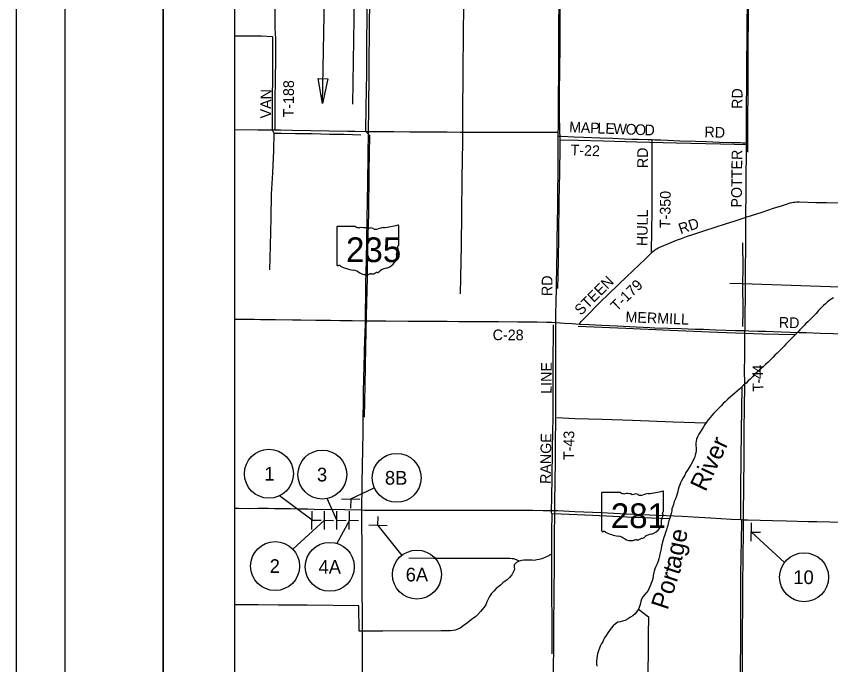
# Model space of a CAD drawing. Extents: x 0 to 680, y 0 to 834.
# Drawn here: x 0 to 166.4, y 90.7 to 223.2 of the extents above; entities that cross this region are included whole.
import ezdxf

# ---------------------------------------------------------------- set-up
doc = ezdxf.new("R2010")
doc.units = 0
for name, color, linetype in [('GM_X_County_Road', 7, 'Continuous'), ('GM_X_County_Road_Text', 7, 'Continuous'), ('GM_X_Interstate_Route', 7, 'Continuous'), ('GM_X_Major_River', 7, 'Continuous'), ('GM_X_Major_River_Text', 7, 'Continuous'), ('GM_X_Minor_River', 7, 'Continuous'), ('GM_X_State_Location', 7, 'Continuous'), ('GM_X_State_Route', 7, 'Continuous'), ('GM_X_State_Shield', 7, 'Continuous'), ('GM_X_Township_Road', 7, 'Continuous'), ('GM_X_Township_Road_Text', 7, 'Continuous'), ('SH_Border', 7, 'Continuous'), ('SH_Cut_Line', 7, 'Continuous'), ('SH_Text', 7, 'Continuous')]:
    doc.layers.add(name, color=color, linetype=linetype)

msp = doc.modelspace()

# ---------------------------------------------------------------- linework, layer by layer
at = {"layer": 'GM_X_County_Road'}
for points in [[(44.69, 161.35), (46.07, 161.33), (47.26, 161.32), (48.69, 161.31), (49.88, 161.28), (52.99, 161.27), (56.45, 161.22), (58.12, 161.19), (61.22, 161.13), (64.21, 161.1), (66.11, 161.07), (68.62, 161.02), (71.25, 160.98), (71.35, 160.98)], [(71.35, 160.98), (73.16, 160.98), (75.54, 160.96), (80.08, 160.94), (84.25, 160.92), (88.07, 160.89), (90.34, 160.88), (95.12, 160.84), (98.58, 160.82), (102.52, 160.79), (105.5, 160.77), (106.45, 160.78), (108.36, 160.74), (108.93, 160.73), (109.44, 160.71), (110.27, 160.65)], [(110.27, 160.65), (112.06, 160.51), (113.6, 160.41), (115.07, 160.33)], [(115.07, 160.33), (115.27, 160.32), (117.06, 160.24), (119.68, 160.11), (121.23, 160.03), (122.9, 159.95), (124.09, 159.89), (125.29, 159.84), (129.46, 159.61), (130.41, 159.57), (135.9, 159.4), (138.76, 159.31), (140.43, 159.26), (142.94, 159.17), (146.99, 159.03), (148.42, 158.99), (148.93, 158.98)], [(148.93, 158.98), (149.74, 158.96), (151.64, 158.89), (153.2, 158.84), (154.75, 158.78), (156.29, 158.75), (160, 158.63), (161.43, 158.58), (164.29, 158.48), (166.91, 158.38), (168.34, 158.34), (170.85, 158.25), (173.59, 158.14), (175.02, 158.09), (178.24, 157.97), (186.12, 157.68), (187.64, 157.62)]]:
    msp.add_lwpolyline(points, dxfattribs=at)
at = {"layer": 'GM_X_Interstate_Route'}
msp.add_lwpolyline([(44.69, 394.07), (374.69, 394.07), (374.69, 64.07), (44.69, 64.07)], close=True, dxfattribs=at)
at = {"layer": 'GM_X_Major_River'}
for points in [[(166.98, 165.7), (166.35, 165.28), (165.81, 164.85), (165.34, 164.44), (164.96, 164.12), (164.42, 163.56), (163.95, 163.09), (163.44, 162.49), (163.03, 162.1), (162.61, 161.62), (162.14, 161.17), (161.73, 160.77), (161.37, 160.42), (161.03, 160.05), (160.52, 159.54), (160.12, 159.14), (159.66, 158.59), (158.79, 157.73), (158.36, 157.28), (157.8, 156.76), (157.29, 156.25), (156.92, 155.84), (156.44, 155.35), (155.93, 154.82), (155.48, 154.39), (155.04, 153.95), (154.59, 153.47), (154.06, 152.95), (153.65, 152.51), (153.09, 152.05), (152.63, 151.58), (152.17, 151.2), (151.81, 150.93), (151.4, 150.52), (150.89, 150.01), (150.44, 149.57), (149.97, 149.09), (149.6, 148.72), (149.14, 148.26), (148.64, 147.83), (148.27, 147.48), (147.84, 147.12), (147.34, 146.62), (146.86, 146.2), (146.37, 145.79), (145.97, 145.43), (145.4, 144.96), (144.87, 144.45), (144.49, 144.09), (144.05, 143.64), (142.96, 142.53)], [(142.96, 142.53), (142.53, 142.1), (142.15, 141.61), (141.81, 141.22), (141.42, 140.75), (141.06, 140.29), (140.73, 139.81), (140.42, 139.33), (140.09, 138.76), (139.75, 138.25), (139.49, 137.79), (139.24, 137.29), (139.02, 136.81), (138.93, 136.42), (138.86, 135.97), (138.86, 135.5), (138.94, 134.94), (138.94, 134.49), (138.89, 134.01), (138.77, 133.55), (138.57, 133.01), (138.34, 132.49), (138.12, 132.04), (137.84, 131.55), (137.52, 130.99), (137.17, 130.47), (136.86, 129.97), (136.6, 129.46), (136.32, 128.91), (135.96, 128.32), (135.72, 127.87), (135.58, 127.45), (135.38, 126.96), (135.24, 126.5), (135.18, 126.12), (135.05, 125.64), (134.9, 125.12), (134.7, 124.62), (134.47, 124.09), (134.32, 123.48), (134.18, 123.05), (134, 122.54), (133.95, 122.16), (133.84, 121.62), (133.71, 121.16), (133.53, 120.67), (133.37, 120.14), (133.23, 119.56), (133.14, 119.17), (133.03, 118.79), (132.86, 118.26), (132.69, 117.75), (132.51, 117.23), (132.36, 116.71), (132.22, 116.23), (132.09, 115.85), (131.98, 115.39), (131.88, 114.98), (131.76, 114.41), (131.64, 113.82), (131.53, 113.33), (131.43, 112.86), (131.34, 112.34), (131.21, 111.87), (131, 111.34), (130.71, 110.79), (130.52, 110.27), (130.36, 109.8), (130.24, 109.31), (130.14, 108.83), (130.09, 108.32), (129.97, 107.86), (129.78, 107.37), (129.59, 106.97), (129.36, 106.37), (129.1, 105.89), (128.78, 105.44), (128.45, 105.06), (128.06, 104.6), (127.79, 104.09), (127.62, 103.6), (127.47, 103), (127.31, 102.42), (127.13, 102.03), (126.83, 101.56), (126.45, 101.11), (125.97, 100.71), (125.49, 100.4), (124.88, 100.04), (124.43, 99.77), (123.9, 99.61), (123.38, 99.5), (122.95, 99.37), (122.46, 99.05), (121.97, 98.63), (121.56, 98.15), (121.22, 97.7), (120.86, 97.24), (120.52, 96.69), (120.18, 96.22), (119.99, 95.8)], [(119.99, 95.8), (119.84, 95.39), (119.62, 95.02), (119.33, 94.53), (119.16, 94.08), (118.97, 93.54), (118.77, 92.95), (118.69, 92.51), (118.63, 92.03), (118.58, 91.46), (118.59, 90.91), (118.61, 90.4)]]:
    msp.add_lwpolyline(points, dxfattribs=at)
at = {"layer": 'GM_X_Minor_River'}
for points in [[(92.3, 320.37), (92.2, 311.07), (92.09, 303.82), (91.99, 294.71), (91.89, 283.03), (91.78, 275.5), (91.7, 266.96), (91.6, 257.68), (91.54, 248.37), (91.45, 240.55), (91.44, 230.55), (91.36, 219.85), (91.29, 211.97), (91.2, 203.05), (91.21, 197.47), (91.04, 190.19), (90.98, 182.86), (90.9, 176.37), (90.73, 166.48)], [(149.64, 235.45), (149.57, 227.15), (149.53, 213.12), (149.42, 196.92), (149.44, 195.48)], [(110.7, 167.6), (110.82, 173.02), (110.9, 178.6), (110.93, 185.45), (111.06, 191.27), (111.12, 196.57), (111.12, 197.94), (111.04, 202.58), (111.03, 207.65), (111.14, 217.07), (111.18, 222.25), (111.21, 228.21)], [(71.71, 227.13), (71.59, 218.3), (71.57, 211.69), (71.43, 204.6), (71.38, 199.77), (72.18, 198.96), (72.04, 191.47), (71.97, 182.83), (71.76, 176.4), (71.68, 169.69), (71.52, 162.05), (71.36, 155.58), (71.21, 147.86), (71.09, 141.27)], [(44.69, 219.23), (46.26, 219.23), (50.09, 219.21), (52.33, 219.07), (52.39, 215.63), (52.33, 210.78), (52.31, 206.5), (52.29, 201.79), (52.31, 200.04), (52.62, 199.34), (54.19, 199.32), (57.04, 199.26), (60.45, 199.25), (64.02, 199.11), (66.99, 199.14), (70.39, 198.98)], [(52.62, 199.34), (52.54, 195.77), (52.38, 191.22), (52.12, 186.88), (52.04, 182.05), (51.87, 176.34), (51.74, 171.44)], [(143.92, 197.1), (134.84, 197.28), (126.8, 197.53), (120.03, 197.68), (114.76, 197.85), (111.12, 197.94)], [(149.42, 196.92), (143.92, 197.1)], [(148.42, 176.94), (148.45, 171.85), (148.42, 168.53), (148.47, 163.06), (148.44, 159.82)], [(168.34, 166.54), (168.3, 167.86), (158.35, 168.24), (148.42, 168.53), (145.85, 168.59)], [(109.75, 160.14), (109.62, 151.56), (109.64, 145.72), (109.62, 141.38), (109.49, 134.83), (109.44, 128.69), (109.41, 125.19), (109.34, 121.82), (109.43, 121.55), (109.35, 117.9), (109.35, 113.27), (109.37, 109.26), (109.4, 104.45), (109.43, 100.49), (109.42, 92.94)], [(143.33, 158.61), (133.64, 159), (124.59, 159.44), (114.81, 159.81)], [(159.16, 158.1), (152.47, 158.25), (143.33, 158.61)], [(148.27, 147.48), (148.14, 138.43), (148.01, 126.88), (148.02, 120.58), (148.21, 120.13), (148.18, 119.76), (148.01, 109.13), (148.02, 96.79), (147.95, 88.72), (147.85, 83.77), (147.87, 81.22), (142.15, 81.47)], [(140.91, 140.07), (134.23, 140.31), (125.95, 140.59), (119.72, 140.8), (114.13, 140.99), (110.44, 141.17)], [(133.49, 120.52), (126.13, 120.82), (117.85, 121.22), (111.35, 121.46), (109.43, 121.55)], [(109.35, 113.27), (108.48, 112.85), (107.88, 112.54), (107.38, 112.34), (106.85, 112.2), (106.4, 112.11), (105.83, 112.03), (105.42, 112.04), (104.97, 112.06), (104.24, 112.07), (103.72, 112.07), (103.25, 112.02), (102.77, 111.89), (102.24, 111.61), (101.78, 111.09), (101.76, 110.66), (101.81, 110.25), (101.7, 109.86), (101.28, 109.05), (100.79, 108.56), (100.29, 108.07), (99.88, 107.77), (99.45, 107.46), (98.96, 106.96), (98.08, 106.27), (97.61, 105.76), (97.13, 105.25), (96.83, 104.88), (96.57, 104.4), (96.36, 103.96), (96.19, 103.54), (95.98, 102.96), (95.65, 102.44), (95.25, 102.05), (94.88, 101.55), (94.33, 100.97), (93.89, 100.57), (93.44, 100.19), (93.05, 99.93), (92.59, 99.59), (92.12, 99.19), (91.57, 98.85), (91.17, 98.5), (90.69, 98.18), (90.22, 97.94), (89.72, 97.8), (89.27, 97.71), (88.77, 97.64), (88.31, 97.63), (87.82, 97.63), (86.81, 97.64)], [(99.4, 112.4), (85.35, 112.43), (80.22, 112.51)], [(102.77, 111.89), (102.21, 112.11), (101.69, 112.32), (101.31, 112.35), (100.86, 112.41), (100.35, 112.43), (99.9, 112.42), (99.4, 112.4)], [(86.81, 97.64), (74.91, 97.55), (70.08, 97.53), (70.03, 102.73), (59.45, 102.85), (53.62, 102.87), (49.42, 102.96), (44.69, 102.97)], [(127.13, 102.03), (129.17, 100.48), (129.11, 96.91), (129.11, 92.94), (129.01, 86.48), (128.98, 82.05), (128.91, 76.47), (128.8, 72.83)]]:
    msp.add_lwpolyline(points, dxfattribs=at)
at = {"layer": 'GM_X_State_Route'}
for points in [[(70.65, 122.33), (70.65, 123.54), (70.68, 126.41), (70.7, 128.08), (70.74, 131.18), (70.82, 134.88), (70.87, 137.98), (70.92, 141.57), (70.94, 143.95), (70.96, 145.5), (70.97, 146.94), (71.02, 148.73), (71.12, 152.19), (71.16, 153.74), (71.19, 154.69), (71.26, 156.96), (71.34, 160.18), (71.35, 160.98), (71.35, 161.85), (71.43, 167.1), (71.46, 168.65), (71.54, 173.31), (71.71, 181.78), (71.84, 189.18), (71.93, 194.79), (71.99, 199.71), (72, 201.12), (72.03, 202.79), (72.04, 204.58), (72.05, 205.77), (72.09, 210.19), (72.1, 211.98), (72.14, 214.96), (72.17, 219.02), (72.2, 222.48), (72.23, 224.99)], [(44.69, 122.67), (45.39, 122.67), (47.42, 122.66), (49.33, 122.67), (51.47, 122.67), (52.79, 122.66), (54.46, 122.64), (56.01, 122.62), (57.92, 122.58), (59.59, 122.55), (60.9, 122.53), (67.11, 122.4), (70.65, 122.33)], [(70.88, 64.07), (70.87, 69.59), (70.85, 72.34), (70.83, 74.48), (70.8, 80.21), (70.8, 81.89), (70.79, 83.67), (70.79, 84.03), (70.78, 85.59), (70.77, 88.09), (70.76, 90.12), (70.73, 95.37), (70.73, 98.36), (70.69, 108.38), (70.68, 110.89), (70.68, 112.68), (70.66, 115.31), (70.64, 119.25), (70.65, 121.99), (70.65, 122.33)], [(70.65, 122.33), (71.16, 122.32), (73.67, 122.31), (78.2, 122.3), (80.71, 122.29), (87.16, 122.27), (89.9, 122.28), (93.72, 122.27), (103.39, 122.26), (105.53, 122.26), (107.68, 122.25), (109.12, 122.24), (110.09, 122.21)], [(110.09, 122.21), (110.67, 122.19), (114.13, 122.05), (119.61, 121.8), (124.62, 121.57), (127.72, 121.44), (132.85, 121.21), (134.39, 121.13), (136.06, 121.05), (138.33, 120.92), (141.9, 120.72), (146.07, 120.48), (148.1, 120.37), (148.63, 120.35), (149.53, 120.32), (154.54, 120.19), (157.4, 120.12), (161.82, 120), (163.61, 119.95), (166.23, 119.89), (169.45, 119.81)]]:
    msp.add_lwpolyline(points, dxfattribs=at)
at = {"layer": 'GM_X_State_Shield'}
for p, q in [((65.49, 180.12), (65.49, 172.44)), ((69.32, 180.25), (65.62, 180.25)), ((78.15, 176.42), (78.15, 180.44)), ((78.15, 176.42), (78.15, 176.42)), ((119.63, 125.77), (119.63, 118.08)), ((123.46, 125.9), (119.75, 125.9)), ((132.29, 122.07), (132.29, 126.09)), ((132.28, 122.07), (132.29, 122.07))]:
    msp.add_line(p, q, dxfattribs=at)
for centre, major_axis, start_param, end_param in [((65.64, 180.14), (0.147, 0), 1.712693, 3.28349), ((70.2, 181.15), (1.42, 0), 4.042523, 4.731795), ((70.68, 175.94), (5.11, 0), 1.404758, 1.657858), ((71.83, 180.18), (0.41, 0), 3.836095, 5.185415), ((72.44, 179.29), (0.853, 0), 0.950623, 2.079405), ((73.54, 180.51), (1.03, 0), 4.081561, 5.145723), ((75.35, 177.91), (2.7, 0), 1.699011, 2.107814), ((73.64, 190.73), (13.42, 0), 4.814394, 5.042369), ((78.01, 180.46), (0.141, 0), 6.141152, 7.989035), ((78.65, 174.74), (0.952, 0), 2.387724, 3.262537), ((78.11, 176.13), (0.218, 0), 1.883978, 3.671073), ((76.73, 175.62), (1.31, 0), 5.934695, 6.695948), ((78, 176.41), (0.151, 0), 5.05454, 6.418171), ((74.39, 174.23), (3.36, 0), 5.101752, 6.440018), ((65.64, 172.42), (0.148, 0), 3.00124, 4.508301), ((65.66, 173.21), (1.13, 0), 4.665946, 4.897461), ((65.89, 171.99), (0.407, 0), 0.519207, 1.627899), ((71.03, 178.9), (9.69, 0), 4.195997, 4.488961), ((75.81, 170.28), (1.84, 0), 1.647645, 2.488434), ((68.14, 168.98), (3.03, 0), 0.823519, 1.323587), ((71.42, 171.96), (1.92, 0), 4.026481, 4.996735), ((72.53, 169.3), (1.58, 0), 1.495662, 1.94098), ((72.67, 171.38), (1.03, 0), 4.691044, 5.507374), ((73.6, 170.64), (0.289, 0), 1.147584, 2.315152), ((73.48, 171.69), (1.08, 0), 4.937069, 5.64225), ((119.77, 125.78), (0.147, 0), 1.712693, 3.28349), ((124.34, 126.79), (1.42, 0), 4.042523, 4.731795), ((124.81, 121.58), (5.11, 0), 1.404758, 1.657858), ((125.97, 125.82), (0.41, 0), 3.836095, 5.185415), ((126.58, 124.93), (0.853, 0), 0.950623, 2.079405), ((127.68, 126.15), (1.03, 0), 4.081561, 5.145723), ((129.49, 123.55), (2.7, 0), 1.699011, 2.107814), ((127.78, 136.37), (13.42, 0), 4.814394, 5.042369), ((132.15, 126.1), (0.141, 0), 6.141152, 7.989035), ((132.25, 121.77), (0.218, 0), 1.883978, 3.671073), ((130.87, 121.26), (1.31, 0), 5.934695, 6.695948), ((132.14, 122.05), (0.151, 0), 5.05454, 6.418171), ((128.53, 119.87), (3.36, 0), 5.101752, 6.440018), ((132.79, 120.39), (0.952, 0), 2.387724, 3.262537), ((119.78, 118.06), (0.148, 0), 3.00124, 4.508301), ((119.8, 118.85), (1.13, 0), 4.665946, 4.897461), ((120.03, 117.64), (0.407, 0), 0.519207, 1.627899), ((125.17, 124.54), (9.69, 0), 4.195997, 4.488961), ((122.28, 114.63), (3.03, 0), 0.823519, 1.323587), ((127.74, 116.28), (0.289, 0), 1.147584, 2.315152), ((127.62, 117.34), (1.08, 0), 4.937069, 5.64225), ((129.94, 115.92), (1.84, 0), 1.647645, 2.488434), ((125.56, 117.6), (1.92, 0), 4.026481, 4.996735), ((126.67, 114.94), (1.58, 0), 1.495662, 1.94098), ((126.81, 117.02), (1.03, 0), 4.691044, 5.507374)]:
    msp.add_ellipse(centre, major_axis=major_axis, ratio=0.8, start_param=start_param, end_param=end_param, dxfattribs=at)
at = {"layer": 'GM_X_Township_Road'}
for points in [[(52.91, 199.99), (52.9, 200.37), (52.89, 201.44), (52.93, 205.86), (52.97, 210.52), (53.01, 214.23), (53.05, 215.42), (53.04, 216.5), (53.03, 218.05), (53.01, 218.65), (52.94, 219.72), (52.9, 220.8), (52.88, 221.99), (52.89, 223.31), (52.93, 226.65), (52.96, 228.33), (53.02, 231.91), (53.04, 234.06), (53.07, 236.57), (53.12, 238.17), (53.13, 238.68)], [(110.77, 199.52), (110.78, 200.47), (110.81, 205.48), (110.85, 212.64), (110.87, 214.79), (110.88, 216.46), (110.89, 219.45), (110.9, 222.19), (110.95, 225.06), (110.96, 226.25), (110.98, 230.55), (110.98, 232.82), (110.99, 234.73), (111, 237.11), (111.02, 237.71), (111.04, 237.83), (111.07, 237.99)], [(149.2, 197.36), (149.2, 198.47), (149.23, 200.61), (149.26, 205.86), (149.28, 208.13), (149.33, 213.86), (149.33, 215.65), (149.34, 216.72), (149.39, 222.21), (149.4, 225.2), (149.41, 227.7), (149.42, 229.49), (149.43, 230.93), (149.45, 232.72), (149.46, 235.34), (149.45, 236.02)], [(44.69, 200.06), (49.35, 200.02), (52.1, 200), (52.91, 199.99)], [(52.91, 199.99), (54.01, 199.99), (56.4, 199.94), (67.75, 199.77), (69.18, 199.75), (71.99, 199.71)], [(71.99, 199.71), (72.76, 199.7), (77.18, 199.66), (80.41, 199.64), (88.05, 199.59), (90.68, 199.56), (93.55, 199.55), (97.73, 199.55), (101.31, 199.53), (109.8, 199.54), (110.51, 199.52), (110.77, 199.52)], [(110.27, 160.65), (110.26, 160.98), (110.29, 162.15), (110.35, 165.14), (110.37, 167.4), (110.4, 168.6), (110.45, 171.7), (110.53, 175.88), (110.56, 177.91), (110.62, 180.65), (110.62, 182.08), (110.64, 183.28), (110.66, 184.47), (110.69, 188.29), (110.72, 190.32), (110.72, 191.04), (110.76, 195.57), (110.76, 197.01), (110.75, 198.56), (110.75, 198.72)], [(110.75, 198.72), (110.76, 199.27), (110.77, 199.52)], [(110.75, 198.72), (111.02, 198.72), (111.38, 198.71), (114, 198.6), (115.91, 198.53), (119.26, 198.4), (121.88, 198.3), (124.27, 198.19), (125.82, 198.12), (127.14, 198.1), (129.05, 198.04), (129.96, 198.02)], [(129.94, 188.15), (129.92, 188.64), (129.92, 191.27), (129.93, 195.21), (129.95, 197.72), (129.95, 197.84), (129.96, 198.02)], [(129.96, 198.02), (130.48, 198), (131.68, 197.95), (133.11, 197.9), (135.62, 197.8), (138.84, 197.68), (140.99, 197.62), (143.74, 197.53), (146.37, 197.44), (147.2, 197.42), (147.56, 197.41), (147.99, 197.4), (148.32, 197.39), (148.55, 197.38), (148.79, 197.37), (149.03, 197.37), (149.2, 197.36)], [(149.11, 182.14), (149.12, 183.07), (149.13, 186.65), (149.15, 189.75), (149.2, 195.96), (149.2, 197.27), (149.2, 197.36)], [(129.8, 174.87), (129.8, 175.14), (129.81, 176.1), (129.87, 178.49), (129.93, 184.34), (129.94, 186.97), (129.94, 187.92), (129.94, 188.15)], [(149.11, 182.14), (150.24, 182.51), (152.4, 183.21), (154.78, 183.98), (156.36, 184.48), (157.38, 184.83), (158.17, 185.09), (158.52, 185.18), (158.81, 185.25), (159.11, 185.27), (159.47, 185.29), (160.06, 185.29), (163.4, 185.2), (165.55, 185.16), (168.18, 185.12)], [(129.8, 174.87), (130.12, 175.16), (130.39, 175.39), (130.68, 175.6), (130.88, 175.73), (131.2, 175.9), (131.53, 176.04), (133.51, 176.88), (134.95, 177.46), (135.95, 177.84), (136.96, 178.19), (138.44, 178.67), (140.93, 179.49), (142.63, 180.05), (145.13, 180.87), (146.72, 181.38), (148.99, 182.1), (149.11, 182.14)], [(148.93, 158.98), (148.93, 159.32), (148.98, 161.71), (149.02, 166.48), (149.02, 167.56), (149.03, 169.7), (149.05, 171.85), (149.08, 175.79), (149.08, 178.65), (149.11, 182.14)], [(115.07, 160.33), (115.22, 160.54), (115.29, 160.63), (115.44, 160.82), (115.85, 161.25), (116.85, 162.27), (118.53, 163.97), (119.55, 164.98), (120.92, 166.31), (123.06, 168.38), (124.69, 169.96), (128.57, 173.67), (129.77, 174.84), (129.8, 174.87)], [(110.09, 122.21), (110.09, 122.32), (110.09, 122.78), (110.09, 123.38), (110.15, 128.63), (110.19, 131.85), (110.2, 133.29), (110.22, 136.75), (110.26, 140.21), (110.25, 141.64), (110.26, 143.67), (110.27, 146.42), (110.27, 148.45), (110.28, 150.95), (110.28, 153.1), (110.29, 154.42), (110.29, 156.56), (110.29, 158.35), (110.29, 160.26), (110.27, 160.65)], [(148.77, 138.7), (148.78, 139.39), (148.82, 142.5), (148.83, 144.17), (148.87, 146.79), (148.88, 147.63), (148.86, 148.82), (148.84, 150.25), (148.89, 154.19), (148.91, 157.29), (148.92, 158.73), (148.93, 158.98)], [(148.63, 120.35), (148.63, 120.54), (148.63, 121.02), (148.64, 122.69), (148.67, 125.91), (148.69, 128.89), (148.72, 131.16), (148.72, 132.11), (148.75, 135.22), (148.77, 138.7)], [(109.82, 83.41), (109.79, 84.84), (109.78, 86.63), (109.8, 88.77), (109.81, 90.68), (109.83, 93.55), (109.85, 96.53), (109.87, 99.52), (109.91, 104.29), (109.93, 107.16), (109.96, 109.43), (109.96, 111.69), (109.98, 114.44), (110.02, 118.26), (110.05, 120.53), (110.09, 122.21)], [(148.35, 81.83), (148.35, 83.19), (148.36, 84.5), (148.36, 85.45), (148.37, 87.6), (148.39, 90.47), (148.42, 95.36), (148.42, 97.51), (148.43, 99.06), (148.47, 101.09), (148.48, 102.16), (148.49, 103.59), (148.51, 107.41), (148.53, 112.07), (148.56, 113.74), (148.61, 116.84), (148.61, 118.63), (148.63, 120.06), (148.63, 120.35)]]:
    msp.add_lwpolyline(points, dxfattribs=at)
at = {"layer": 'SH_Border'}
for points in [[(10, 430), (30, 430), (30, 10), (10, 10)], [(30, 430), (670, 430), (670, 10), (30, 10)]]:
    msp.add_lwpolyline(points, close=True, dxfattribs=at)
at = {"layer": 'SH_Cut_Line'}
msp.add_lwpolyline([(0, 0), (680, 0), (680, 440), (0, 440)], close=True, dxfattribs=at)
at = {"layer": 'SH_Text'}
for p, q in [((62.6, 205.43), (63.08, 231.05)), ((69.15, 230.92), (68.68, 205.29)), ((68.35, 124.58), (73.17, 126.85)), ((60.45, 120.23), (53.78, 125.23)), ((65.53, 120.22), (63.5, 124.65)), ((66.47, 124.62), (70.22, 124.55)), ((68.35, 124.58), (68.31, 122.71)), ((60.43, 118.35), (60.46, 122.11)), ((62.98, 118.35), (63, 122.1)), ((65.52, 118.35), (65.54, 122.1)), ((68.06, 118.34), (68.09, 122.1)), ((62.99, 120.23), (56.52, 114.3)), ((60.45, 120.23), (62.32, 120.22)), ((62.99, 120.23), (64.86, 120.21)), ((68.07, 120.22), (65.52, 115.5)), ((65.53, 120.22), (67.41, 120.21)), ((68.07, 120.22), (69.95, 120.21)), ((73.89, 119.13), (73.96, 121.01)), ((75.77, 119.06), (72.02, 119.2)), ((73.9, 119.15), (78.76, 113.04)), ((150.19, 115.93), (150.26, 119.69)), ((150.23, 117.81), (152.1, 117.78)), ((157.02, 111.62), (150.23, 117.81))]:
    msp.add_line(p, q, dxfattribs=at)
msp.add_lwpolyline([(63.7, 210.45), (62.6, 205.43), (61.69, 210.49)], close=True, dxfattribs=at)
for centre in [(51.63, 129.74), (62.54, 129.56), (77.74, 128.9), (52.89, 110.86), (64.06, 110.71), (81.88, 109.13), (160.99, 108.59)]:
    msp.add_circle(centre, 5, dxfattribs=at)

# ---------------------------------------------------------------- texts
at = {"layer": 'GM_X_County_Road_Text'}
for s, rotation, p in [('MERMILL', 357.6137, (124.46, 160.73)), ('RD', 358.0314, (155.8, 159.61)), ('C-28', 359.6571, (97.35, 157.04))]:
    msp.add_text(s, height=2.182, rotation=rotation, dxfattribs=at).set_placement(p)
at = {"layer": 'GM_X_Major_River_Text'}
for s, rotation, p in [('River', 64.8218, (140.85, 125.91)), ('age', 78.6554, (135.69, 110.14)), ('Port', 71.6564, (133.07, 101.74))]:
    msp.add_text(s, height=3.639, rotation=rotation, dxfattribs=at).set_placement(p)
at = {"layer": 'GM_X_State_Location'}
for s, p in [('235', (68.83, 161.9)), ('281', (136.93, 119.46))]:
    msp.add_text(s, height=0.00727, rotation=0, dxfattribs=at).set_placement(p)
for s, p in [('s', (71.4, 162.42)), ('r', (71.4, 162.42)), ('s', (139.49, 119.99)), ('r', (139.49, 119.99))]:
    msp.add_text(s, height=0.00727, dxfattribs=at).set_placement(p)
at = {"layer": 'GM_X_State_Shield'}
for s, p in [('235', (67.38, 172.98)), ('281', (121.49, 118.62))]:
    msp.add_text(s, height=5.063, dxfattribs=at).set_placement(p)
at = {"layer": 'GM_X_Township_Road_Text'}
for s, height, rotation, p in [('T-188', 2.182, 89.7193, (56.71, 202.54)), ('VAN', 2.182, 89.6836, (52.07, 202.34)), ('RD', 2.182, 89.5063, (148.39, 204.29)), ('M', 2.18, 357.8463, (112.96, 199.51)), ('A', 2.18, 357.8467, (115.33, 199.42)), ('P', 2.18, 357.8471, (117.24, 199.35)), ('L', 2.18, 357.8438, (118.72, 199.29)), ('E', 2.18, 357.8476, (120.35, 199.23)), ('W', 2.18, 357.8471, (121.98, 199.17)), ('O', 2.18, 357.843, (124.5, 199.08)), ('O', 2.18, 357.8551, (126.42, 199)), ('D', 2.18, 358.2229, (128.36, 198.93)), ('RD', 2.182, 358.0243, (140.6, 198.52)), ('T-22', 2.182, 357.8736, (113.24, 194.84)), ('RD', 2.182, 90, (129.09, 192.19)), ('POTTER', 2.182, 89.4549, (148.26, 184.12)), ('T-350', 2.182, 89.4394, (133.67, 179.91)), ('HULL', 2.182, 89.2262, (128.99, 176.26)), ('RD', 2.182, 18.439, (135.76, 178.69)), ('RD', 2.182, 89.0155, (109.51, 166.03)), ('STEEN', 2.182, 44.8436, (115.38, 161.97)), ('T-179', 2.182, 44.0089, (122.73, 162.78)), ('LINE', 2.182, 89.7142, (109.41, 146.07)), ('4', 2.18, 89.3026, (152.63, 150.4)), ('4', 2.18, 90.4111, (152.64, 149.07)), ('T', 2.18, 90.9558, (152.68, 146.55)), ('-', 2.18, 90.8197, (152.65, 148.18)), ('T-43', 2.182, 89.6614, (113.99, 132.51)), ('RANGE', 2.182, 89.2026, (109.22, 127.63))]:
    msp.add_text(s, height=height, rotation=rotation, dxfattribs=at).set_placement(p)
at = {"layer": 'SH_Text'}
for s, p in [('1', (50.69, 128.34)), ('3', (61.45, 128.16)), ('8B', (75.34, 127.5)), ('2', (51.79, 109.46)), ('4A', (61.77, 109.31)), ('6A', (79.58, 107.73)), ('10', (158.8, 107.19))]:
    msp.add_text(s, height=2.8, dxfattribs=at).set_placement(p)

doc.saveas('drawing.dxf')
